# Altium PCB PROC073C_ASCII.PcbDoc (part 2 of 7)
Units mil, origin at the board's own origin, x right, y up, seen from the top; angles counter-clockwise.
Board outline 2165.35 x 2695.12 mil, 8 copper layers (Top Layer, L2_GND, L3_SIGNAL 1, L4_SIGNAL 2, L5_SIGNAL 3, L6_SIGNAL 4, L7_GND, Bottom Layer), stack 55.9 mil thick; 393 components, 319 nets, 1311 pads, 1643 vias.
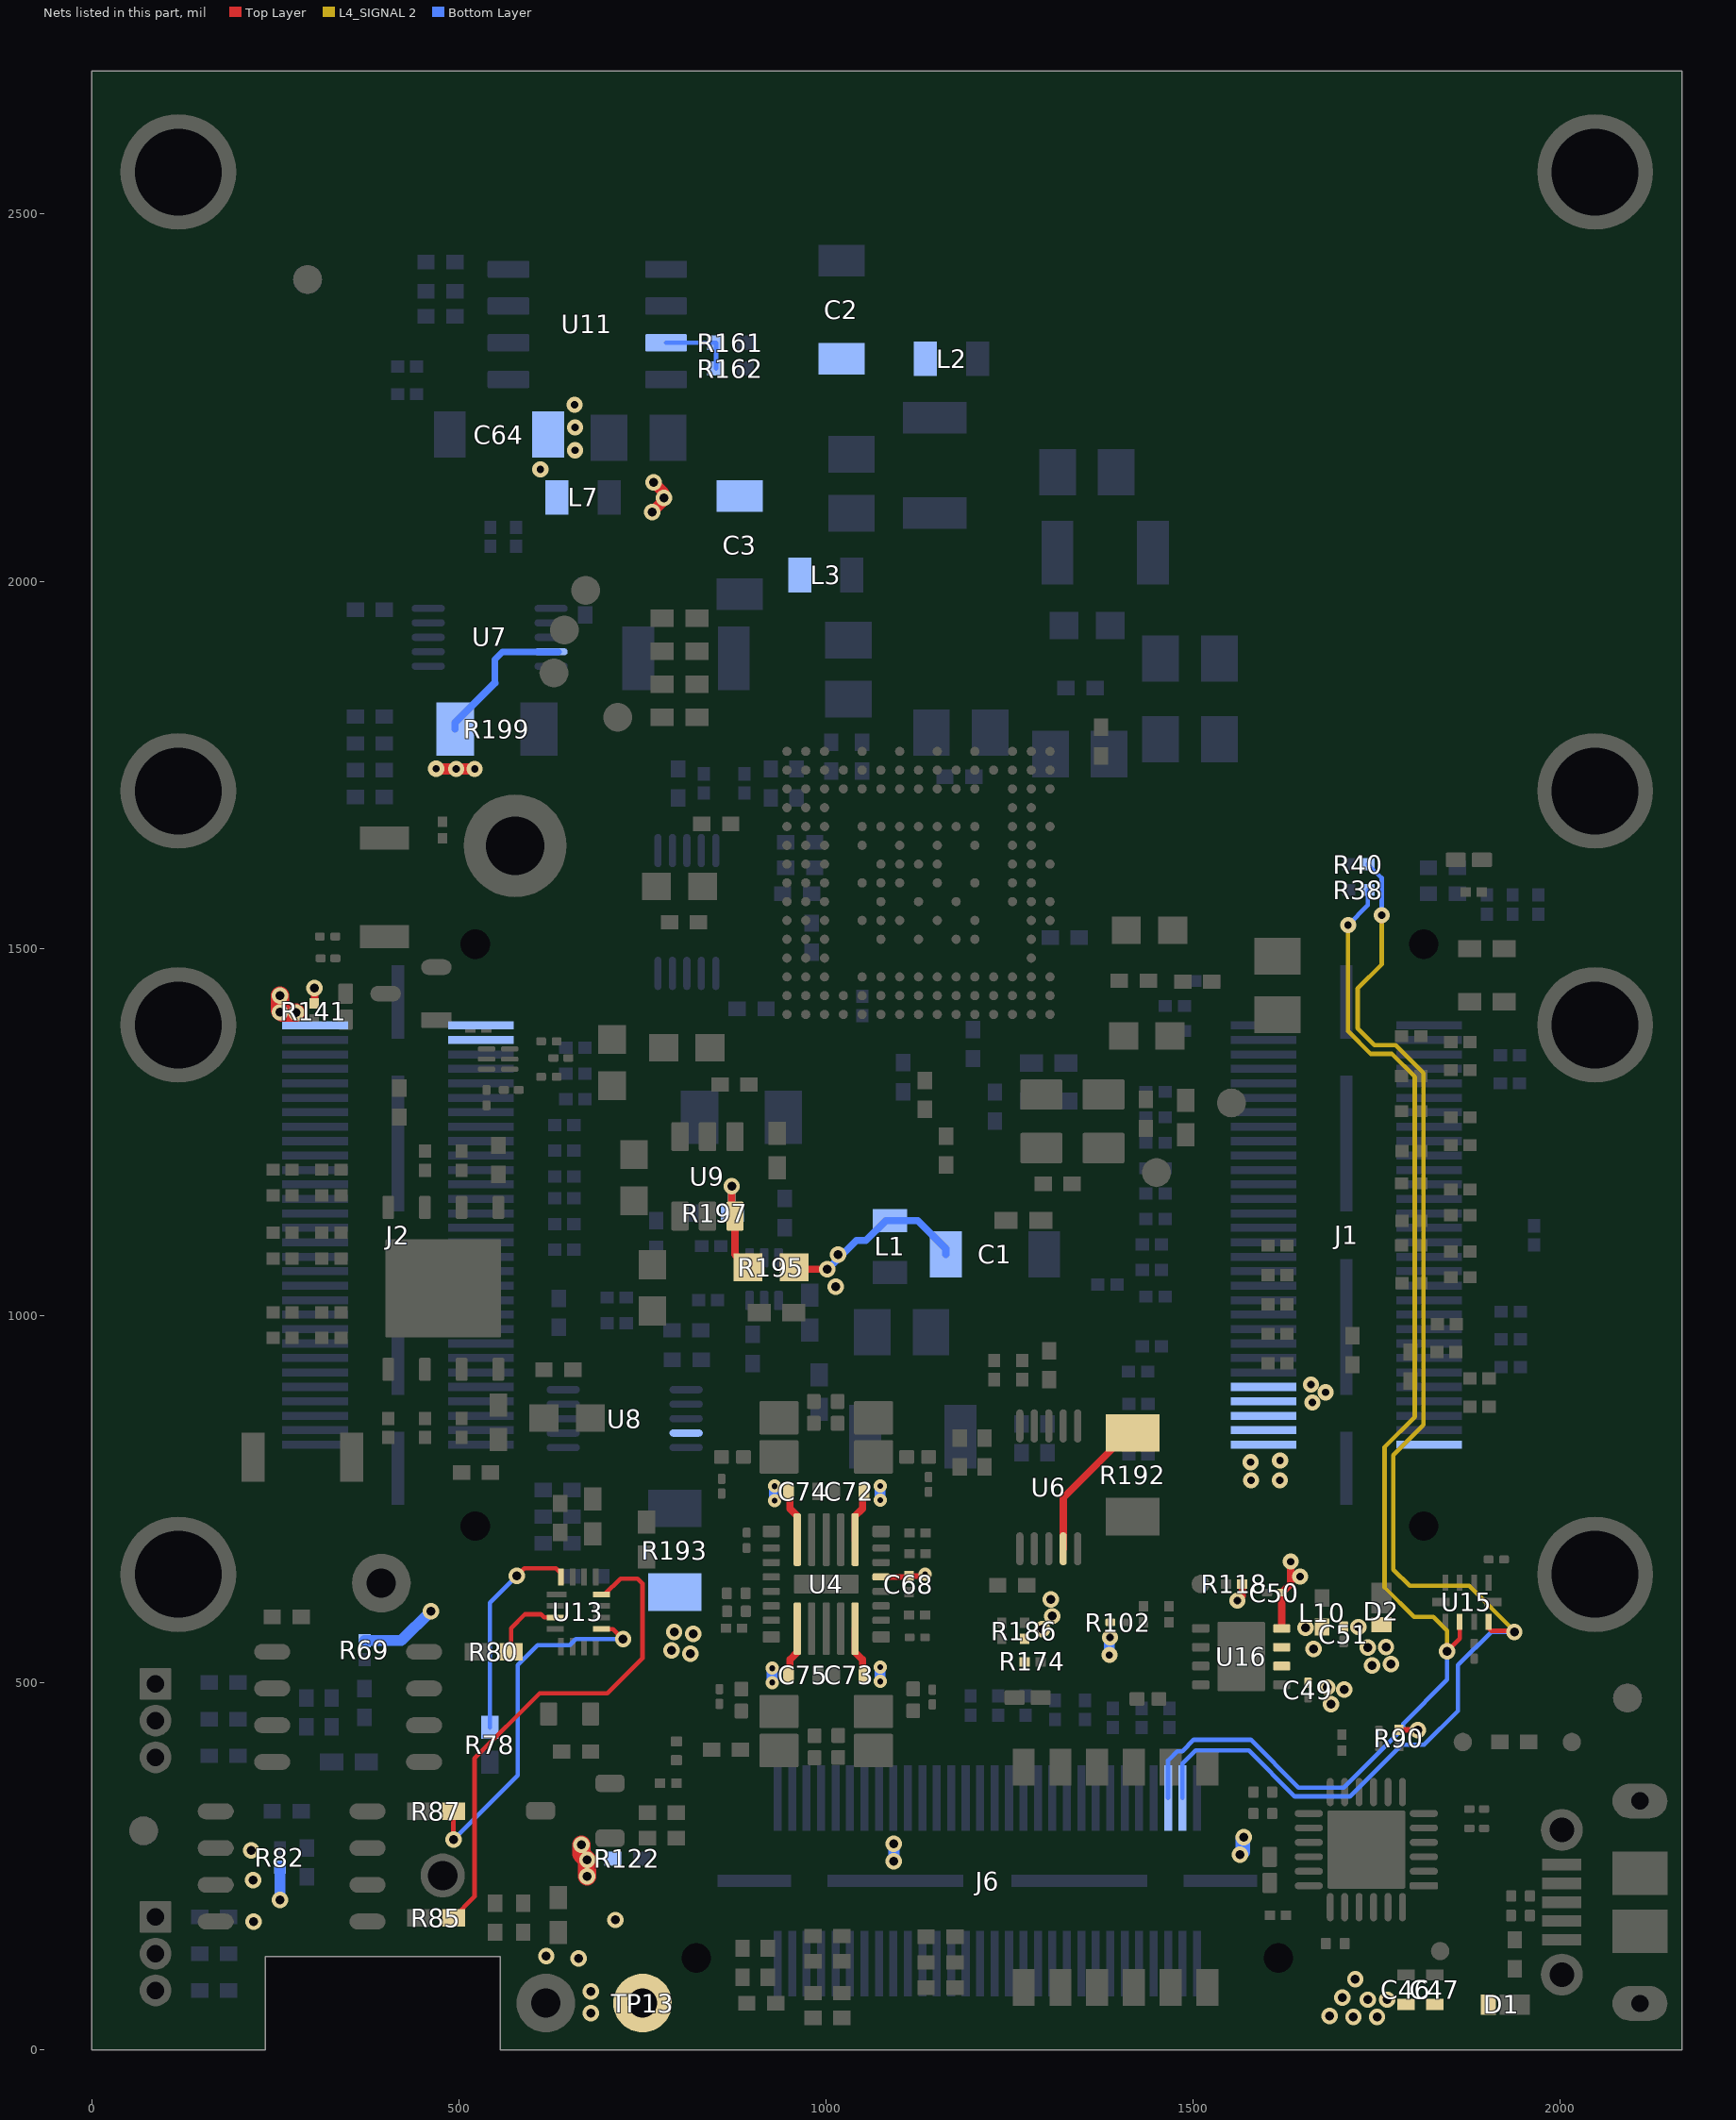
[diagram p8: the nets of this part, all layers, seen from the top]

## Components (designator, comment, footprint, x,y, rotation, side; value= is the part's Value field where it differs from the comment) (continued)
R171 "RC0201JR-07510RL" 0201L 526.8,1391.99 r180 top
R172 "ERJ-2GEJ511X" 0402L 659.82,406.64 r180 top
R173 "RC0402FR-073R83L" "FP-RC0402FR-073R83L_0402 (1005 Metric)-IPC_C" 884.8,476.65 r270 top
R174 "RC0201JR-07510RL" 0201L 1281.31,528.75 r0 top
R175 "RC0402FR-073R83L" "FP-RC0402FR-073R83L_0402 (1005 Metric)-IPC_C" 1118.8,476.93 r270 top
R176 "RC0201FR-074K99L" 0201L 1123.96,592.5 r0 top
R177 "RC0201FR-074K99L" 0201L 1124.8,676.01 r0 top
R178 "RC0402FR-073R83L" "FP-RC0402FR-073R83L_0402 (1005 Metric)-IPC_C" 872.8,807.65 r0 top
R179 "ERJ-2GEJ511X" 0402L 776.61,288.6 r180 top
R180 "RC0201JR-070RL" "FP-RC0201JR-070RL_0201 (0603 Metric)-MFG" 878.14,597.5 r0 top
R181 "RC0201JR-070RL" "FP-RC0201JR-070RL_0201 (0603 Metric)-MFG" 877.8,622 r0 top
R182 "CRCW0402100KFKED" 0402L 776.6,323.18 r0 top
R183 "RC0402FR-073R83L" "FP-RC0402FR-073R83L_0402 (1005 Metric)-IPC_C" 1124.8,807.79 r180 top
R184 "CRCW040210K0JNED" 0402 1303.12,1292.36 r180 bottom
R185 "CRCW04020000Z0ED" 0402 1303.12,1344.13 r180 bottom
R186 "RC0201JR-071KL" 0201L 1270.29,570.95 r270 top
R187 "RC0201FR-074K99L" 0201L 1124.8,704.35 r0 top
R188 "RC0201FR-074K99L" 0201L 874.94,574.5 r180 top
R189 "RR0306P-103-D" FP-RR0306P-103-D_0201-IPC_C 1124.42,562 r0 top
R190 "RR0306P-103-D" FP-RR0306P-103-D_0201-IPC_C 891.97,694.21 r90 top
R191 "RCS06030000Z0EA" 0603 738.67,1187.92 r90 top
R192 "PMR18EZPFV2L00" 1206 1417.66,783.38 r90 top
R193 "PMR18EZPFV2L00" 1206 794.24,680.61 r270 bottom
R194 "RC0201FR-071K96L" 0201L 1239.41,570.95 r90 top
R195 "MCT06030Z0000ZP500" 0603 925.25,1065.92 r180 top
R196 "CRCW0402510RJNED" 0402 932.6,1004.37 r180 top
R197 "ERJ-2RKF1003X" 0402 848.74,1139.77 r0 bottom
R198 "RC0201JR-070RL" "FP-RC0201JR-070RL_0201 (0603 Metric)-MFG" 796.29,407.65 r90 top
R199 "PMR18EZPFV2L00" 1206 552.07,1798.74 r180 bottom
R200 "PMR18EZPFV2L00" 1206 884.81,1270.12 r0 bottom
R201 "CRCW0201100KFKED" 0201L 785.2,363.4 r0 top
R202 "ERJ-2GE0R00X" 0402L 911.88,64.04 r180 top
R203 "CRCW040210K0FKED" 0402L 1002.05,77.62 r0 top
R204 "CRCW04027K87FKED" 0402L 1155.97,85.15 r0 top
R205 "CRCW040282K5FKED" 0402L 1002.05,43.89 r0 top
R206 "CRCW040210K0FKED" 0402L 920.56,118.98 r270 top
R207 "CRCW04027K87FKED" 0402L 1155.97,119.47 r0 top
R208 "CRCW040282K5FKED" 0402L 886.26,118.98 r270 top
R209 "CRCW040210K0FKED" 0402L 1002.05,155.42 r0 top
R210 "CRCW04027K87FKED" 0402L 1155.97,154.42 r0 top
R211 "CRCW040282K5FKED" 0402L 1002.05,120.94 r0 top
R212 "RC0201JR-07220RL" 0201L 1882,1576.82 r180 top
R213 "RC0201JR-07220RL" 0201L 477.94,1661.26 r90 top
R214 "RC0201JR-070RL" "FP-RC0201JR-070RL_0201 (0603 Metric)-IPC_C" 321.89,1486.65 r180 top
R215 "RR0306P-103-D" FP-RR0306P-103-D_0201-IPC_C 321.39,1516.38 r0 top
R216 "ERJ-2GE0R00X" 0402 635.54,184.1 r90 top
R217 "CRCW02010000Z0ED" 0201_Silk 326.6,1198.84 r180 top locked
R218 "CRCW02010000Z0ED" 0201_Silk 326.6,1163.84 r180 top locked
R219 "CRCW02010000Z0ED" 0201_Silk 1797.27,1044.56 r0 top
R220 "CRCW02010000Z0ED" 0201_Silk 1796.85,1095.72 r0 top
R221 "CRCW02010000Z0ED" 0201_Silk 326.6,1113.02 r180 top locked
R222 "CRCW02010000Z0ED" 0201_Silk 326.6,1078.02 r180 top locked
R223 "CRCW02010000Z0ED" 0201_Silk 326.6,1004.77 r180 top locked
R224 "CRCW02010000Z0ED" 0201_Silk 326.6,969.77 r180 top locked
R225 "CRCW02010000Z0ED" 0201_Silk 1797.27,1129.03 r0 top
R226 "CRCW02010000Z0ED" 0201_Silk 1796.85,1180.18 r0 top
R227 "CRCW02010000Z0ED" 0201_Silk 1797.27,1224.38 r0 top
R228 "CRCW02010000Z0ED" 0201_Silk 1796.85,1278.52 r0 top
R229 "CRCW02010000Z0ED" 0201_Silk 1796.85,1326.22 r0 top
R230 "CRCW02010000Z0ED" 0201_Silk 1796.85,1380.71 r0 top
S1 "218-6LPST" SW_218-6LPST 1394.21,235.15 r90 top locked
S2 "B3U-1000P" SW_B3U-1000P 287.11,807.23 r0 top
S3 "B3U-1000P" SW_B3U-1000P 398.63,1583.31 r90 top
TP1 "TESTPOINT" TP_25MIL-SMT 1836.32,134.9 r270 top
TP2 "TP_SM_1MM" TP_SM_1MM 672.85,1987.78 r90 top
TP3 "TP_SM_1MM" TP_SM_1MM 643.74,1933.67 r90 top
TP4 "TP_SM_1MM" TP_SM_1MM 716.44,1814.77 r90 top
TP5 "TP_SM_1MM" TP_SM_1MM 629.51,1875.39 r90 top
TP6 "TP_SM_1MM" TP_SM_1MM 1552,1289.77 r90 top
TP7 "TP_SM_1MM" TP_SM_1MM 1450,1194.77 r90 top
TP8 "TESTPOINT" TP_25MIL-SMT 1510.32,634.76 r90 top
TP9 "TESTPOINT" TP_25MIL-SMT 2015.61,419.58 r0 top
TP10 "TESTPOINT" TP_25MIL-SMT 1867.15,419.58 r0 top
TP11 "TESTPOINT" TP_VIA_060RND040 478.18,237.78 r180 top
TP12 "5001" Keystone5001 618.57,64.04 r0 top
TP13 "5001" Keystone5001 750.27,64.04 r0 top
TP14 "5001" Keystone5001 394.54,635.9 r0 top
U1 "IWR6843QAGABL" ABL0161B 1125.98,1589.39 r270 top
U2 "MX25V1635FZNQ" WSON-8L_6x5MM_EP 478.88,1037.19 r270 top
U3 "TMP112AQDRLRQ1" DRL0006A 915.74,1049.77 r270 bottom
U4 "LP87524JRNFRQ1" RNF0026C 1000.33,634.48 r0 top
U5 "TCAN1042HGVDQ1" D0008A_L 349.29,467.41 r180 top
U6 "INA226AIDGST" DGS0010A_L 1303.36,766.27 r270 top
U7 "INA226AIDGST" DGS0010A_L 542.07,1923.74 r0 bottom
U8 "INA226AIDGST" DGS0010A_L 725.86,859.9 r0 bottom
U9 "TPS22917DBVR" DBV0006A_N 838.74,1189.77 r90 top
U10 "INA226AIDGST" DGS0010A_L 810.59,1549.77 r270 bottom
U11 "CAT24C08WI-GT3" SOIC-8 675,2349.77 r180 bottom
U12 "TCAN1042HGVDQ1" D0008A_L 272.44,250.13 r180 top
U13 "TS3A5018RSVR" RSV0016A 662.79,596.95 r0 top
U14 "CP2105-F01-GMR" FP-CP2105-F01-GMR_QFN24-EP-IPC_A 1735.81,273.04 r180 top
U15 "TS5A23157RSER" RSE0010A 1872.76,609.98 r270 top
U16 "TPS2115ADRBR" DRB0008B 1565.44,535.87 r0 top
U17 "SN74LVC1G11DSFR" DSF0006A 553.57,1349.48 r180 top
Y1 "CX3225SA40000D0PTWCC" Kyocera_CX3225SA 1335.59,1264.77 r90 top
ZZ1 "This Assembly Note is for PCB labels only" AssemblyNoteLabel -833.57,3597.27 r0 top
ZZ2 "These assemblies are ESD sensitive, ESD precautions shall be observed." AssemblyNote -831.16,3520.11 r0 top
ZZ3 "These assemblies must be clean and free from flux and all contaminants. Use of no clean flux is not acceptable." AssemblyNote -831.16,3433.3 r0 top
ZZ4 "These assemblies must comply with workmanship standards IPC-A-610 Class 2, unless otherwise specified." AssemblyNote -835.98,3341.67 r0 top
ZZ5 "INDICATION FOR COMPONENTS D* ARE GIVEN AT THEIR CATHODE SIDE." AssemblyNote -834.59,3254.07 r0 top

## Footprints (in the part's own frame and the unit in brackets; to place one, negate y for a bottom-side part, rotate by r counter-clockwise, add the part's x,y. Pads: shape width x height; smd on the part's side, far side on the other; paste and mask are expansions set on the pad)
0201 [mm] "Data from Kemet datasheet CC101_COM dated 7/28/11"
  rect 0.46x0.42 smd mask+0: 1(-0.33,0) 2(0.33,0)
0201_033 [mm] "SMD, 2-Leads, Height 0.33mm"
  rect 0.46x0.42 smd mask+0: 1(-0.33,0) 2(0.33,0)
0201_033L [mm] "0201"
  rect 0.36x0.32 smd mask+0: 1(-0.28,0) 2(0.28,0)
0201_Silk [mm] "Data from Kemet datasheet CC101_COM dated 7/28/11"
  rect 0.46x0.42 smd mask+0: 1(-0.33,0) 2(0.33,0)
  silkscreen extent -0.75,-0.4 0.75,0.4
0201L [mm] "Data from Kemet datasheet CC101_COM dated 7/28/11"
  rect 0.36x0.32 smd mask+0: 1(-0.28,0) 2(0.28,0)
0402 [mm] "0402 from SM-752 data"
  rect 0.8x0.6 smd: 1(-0.6,0) 2(0.6,0)
  silkscreen extent -1.22,-0.52 1.22,0.52
0402_070 [mil] "SMD, 2-Leads, Body 1.2x0.7mm, Height 0.7mm"
  rect 15x24 smd: 1(-20,0) 2(20,0)
0402L [mm] "0402 from SM-752 data"
  rect 0.6x0.5 smd: 1(-0.5,0) 2(0.5,0)
0603 [mm] "0603 from SM-752 data"
  rect 1x0.95 smd: 1(-0.8,0) 2(0.8,0)
  silkscreen extent -1.52,-0.69 1.52,0.69
0805_HV [mil] "0805 with 30mil clearance between pads"
  rect 50x63 smd: 1(-40,0) 2(40,0)
  silkscreen extent -74,-40 74,40
1206 [mm] "1206 from SM-752 data"
  rect 1.3x1.85 smd: 1(-1.45,0) 2(1.45,0)
  silkscreen extent -2.4,-1.21 2.4,1.21
1206_180 [mm] "1206_180"
  rect 1.1x1.6 smd: 1(-1.7,0) 2(1.7,0)
  silkscreen extent -0.9,-1 0.9,1
1210_280 [mm] "SMD, 2-Leads, Body 3.6x2.8mm, Height 2.8mm"
  rect 1.1x2.2 smd: 1(-1.65,0) 2(1.65,0)
  silkscreen extent -0.84,-1.4 0.84,1.4
ABL0161B [mm] "BGA, 161-Balls, Body 10.4x10.4mm, Pitch 0.65mm"
  round 0.32 smd: A1(-4.55,4.55) A2(-3.9,4.55) A3(-3.25,4.55) A5(-1.95,4.55) A7(-0.65,4.55) A9(0.65,4.55) A10(1.3,4.55) A13(3.25,4.55) A14(3.9,4.55) A15(4.55,4.55) B1(-4.55,3.9) B2(-3.9,3.9) B3(-3.25,3.9) B4(-2.6,3.9) B5(-1.95,3.9) B6(-1.3,3.9) B7(-0.65,3.9) B8(0,3.9) B9(0.65,3.9) B10(1.3,3.9) B11(1.95,3.9) B12(2.6,3.9) B13(3.25,3.9) B14(3.9,3.9) B15(4.55,3.9) C1(-4.55,3.25) C2(-3.9,3.25) C3(-3.25,3.25) C4(-2.6,3.25) C5(-1.95,3.25) C6(-1.3,3.25) C7(-0.65,3.25) C8(0,3.25) C9(0.65,3.25) C13(3.25,3.25) C14(3.9,3.25) C15(4.55,3.25) D2(-3.9,2.6) D13(3.25,2.6) D14(3.9,2.6) D15(4.55,2.6) E1(-4.55,1.95) E2(-3.9,1.95) E3(-3.25,1.95) E5(-1.95,1.95) E6(-1.3,1.95) E8(0,1.95) E10(1.3,1.95) E11(1.95,1.95) E13(3.25,1.95) E14(3.9,1.95) E15(4.55,1.95) F2(-3.9,1.3) F3(-3.25,1.3) F5(-1.95,1.3) F9(0.65,1.3) F11(1.95,1.3) F13(3.25,1.3) F14(3.9,1.3) F15(4.55,1.3) G1(-4.55,0.65) G2(-3.9,0.65) G3(-3.25,0.65) G5(-1.95,0.65) G6(-1.3,0.65) G7(-0.65,0.65) G8(0,0.65) G10(1.3,0.65) G13(3.25,0.65) G14(3.9,0.65) G15(4.55,0.65) H2(-3.9,0) H3(-3.25,0) H5(-1.95,0) H7(-0.65,0) H9(0.65,0) H11(1.95,0) H13(3.25,0) H14(3.9,0) H15(4.55,0) J1(-4.55,-0.65) J2(-3.9,-0.65) J3(-3.25,-0.65) J5(-1.95,-0.65) J6(-1.3,-0.65) J7(-0.65,-0.65) J8(0,-0.65) J10(1.3,-0.65) J13(3.25,-0.65) J14(3.9,-0.65) J15(4.55,-0.65) K2(-3.9,-1.3) K3(-3.25,-1.3) K5(-1.95,-1.3) K7(-0.65,-1.3) K8(0,-1.3) K9(0.65,-1.3) K10(1.3,-1.3) K11(1.95,-1.3) K13(3.25,-1.3) K14(3.9,-1.3) K15(4.55,-1.3) L1(-4.55,-1.95) L2(-3.9,-1.95) L3(-3.25,-1.95) L5(-1.95,-1.95) L6(-1.3,-1.95) L8(0,-1.95) L10(1.3,-1.95) L13(3.25,-1.95) L14(3.9,-1.95) L15(4.55,-1.95) M2(-3.9,-2.6) M3(-3.25,-2.6) M14(3.9,-2.6) M15(4.55,-2.6) N1(-4.55,-3.25) N2(-3.9,-3.25) N3(-3.25,-3.25) N4(-2.6,-3.25) N5(-1.95,-3.25) N6(-1.3,-3.25) N7(-0.65,-3.25) N8(0,-3.25) N9(0.65,-3.25) N10(1.3,-3.25) N11(1.95,-3.25) N12(2.6,-3.25) N13(3.25,-3.25) N14(3.9,-3.25) N15(4.55,-3.25) P1(-4.55,-3.9) P2(-3.9,-3.9) P3(-3.25,-3.9) P4(-2.6,-3.9) P5(-1.95,-3.9) P6(-1.3,-3.9) P7(-0.65,-3.9) P8(0,-3.9) P9(0.65,-3.9) P10(1.3,-3.9) P11(1.95,-3.9) P12(2.6,-3.9) P13(3.25,-3.9) P14(3.9,-3.9) P15(4.55,-3.9) R1(-4.55,-4.55) R2(-3.9,-4.55) R3(-3.25,-4.55) R4(-2.6,-4.55) R5(-1.95,-4.55) R6(-1.3,-4.55) R7(-0.65,-4.55) R8(0,-4.55) R9(0.65,-4.55) R10(1.3,-4.55) R11(1.95,-4.55) R12(2.6,-4.55) R13(3.25,-4.55) R14(3.9,-4.55) R15(4.55,-4.55)
  silkscreen extent -5.3,-5.3 5.3,5.3
APHHS1005_Green [mm] "SMD, 2-Leads, Body 1x0.5mm"
  rrect20% 0.7x0.5 smd: 1(-0.45,0) 2(0.45,0)
  silkscreen extent -0.8,-0.65 1.2,0.65
AssemblyNote [mil] "Assembly Note"
AssemblyNoteLabel [mil] "Assembly Note for PCB Labels"
CE_Mark_5mm [mil] "Minimum text height for CE Mark"
CONN_105017-0001 [mm] "Molex Micro USB-B"
  rect 0.4x1.35 smd: 1(-1.3,1.35) 2(-0.65,1.35) 3(0,1.35) 4(0.65,1.35) 5(1.3,1.35)
  oval 1.2x1.9 hole 0.6 slot 1.3 at 90 deg: 6(-3.5,-1.35) 9(3.5,-1.35)
  rect 1.5x1.9 smd: 7(-1,-1.35) 8(1,-1.35)
  round 1.45 hole 0.85: 10(2.5,1.35) 11(-2.5,1.35)
  Top Layer region: 3.5,-0.4 2.3,-0.4 2.3,-2.3 3.5,-2.3
  Top Layer region: -3.5,-2.3 -2.3,-2.3 -2.3,-0.4 -3.5,-0.4
  silkscreen extent -4.1,-0.2 4.1,1.4
D0008A_L [mm] "SOIC, 8-Leads, Body 4.9x3.9mm, Pitch 1.27mm, IPC High Density"
  oval 1.25x0.55 smd: 1(-2.625,1.905) 2(-2.625,0.635) 3(-2.625,-0.635) 4(-2.625,-1.905) 5(2.625,-1.905) 6(2.625,-0.635) 7(2.625,0.635) 8(2.625,1.905)
  silkscreen extent -3.1,-2.5 0.9,2.5
DBV0006A_N [mm] "SOT23, 6-Leads, Body 2.9x1.6mm, Pitch 0.95mm, Lead Span 2.8mm, IPC Medium Density"
  rrect17% 1x0.6 smd: 1(-1.375,0.95) 2(-1.375,0) 3(-1.375,-0.95) 4(1.375,-0.95) 5(1.375,0) 6(1.375,0.95)
  silkscreen extent -1.68,-1.55 0.5,1.55
DGS0010A_L [mm] "TSSOP, 10-Leads, Body 3x3mm, Pitch 0.5mm, IPC High Density"
  oval 1.15x0.25 smd: 1(-2.125,1) 2(-2.125,0.5) 3(-2.125,0) 4(-2.125,-0.5) 5(-2.125,-1) 6(2.125,-1) 7(2.125,-0.5) 8(2.125,0) 9(2.125,0.5) 10(2.125,1)
  silkscreen extent -2.65,-1.55 0.9,1.55
DRB0008B [mm] "SON, 8-Leads, Body 3x3mm, Pitch 0.65mm, Thermal Pad 2.4x1.65mm, TI Recommended"
  rrect33% 0.6x0.3 smd: 1(-1.4,0.975) 2(-1.4,0.325) 3(-1.4,-0.325) 4(-1.4,-0.975) 5(1.4,-0.975) 6(1.4,-0.325) 7(1.4,0.325) 8(1.4,0.975)
  rrect9% 1.47x1.06 on Top Paste: 9(0,-0.63) 9(0,0.63)
  rrect6% 1.65x2.4 smd paste-1.2: 9(0,0)
  silkscreen extent -1.73,-1.73 1.73,1.73
DRL0006A [mm] "SOTFL, 6-Flat Leads, Body 1.2x1.6x0.6mm, Pitch 0.5mm, TI recommended"
  rrect33% 0.67x0.3 smd: 1(-0.74,0.5) 2(-0.74,0) 3(-0.74,-0.5) 4(0.74,-0.5) 5(0.74,0) 6(0.74,0.5)
  silkscreen extent -0.9,-0.95 0.5,0.95
DSF0006A [mm] "TI recommended land pattern"
  rrect59% 0.6x0.17 smd mask+0: 1(-0.4,0.35) 2(-0.4,0) 3(-0.4,-0.35) 4(0.4,-0.35) 5(0.4,0) 6(0.4,0.35)
  silkscreen extent -0.6,-0.63 0.6,0.63
DSN2_0603 [mm] "SMD, 2-Leads, Body 1.6x0.8mm"
  rect 0.52x0.7 smd: 1(-0.64,0)
  rect 1.05x0.7 smd: 2(0.275,0)
  silkscreen extent -1.4,-0.75 0.8,0.75
FCC_disclaimer [mil]
Fiducial10-20 [mm]
  round 1 smd mask+0: 1(0,0)
  Top Layer keep-out circle w1.178: c0,0 r0.5
FP-BSS123-7-F_SOT23-IPC_C [mm]
  rrect18% 1.059x0.547 smd paste+0 mask+0: 1(-0.877,0.915)
  rrect100% 1.059x0.547 smd paste+0 mask+0: 2(-0.877,-0.915) 3(0.877,0)
FP-CL03A105MO3NRNH_0201-IPC_C [mil]
  rrect33% 15.83x11.94 smd paste+0 mask+0: 1(-9.87,0) 2(9.87,0)
"FP-CL05A226MQ5N6J8_0402 (1005 Metric)-IPC_C" [mil]
  rrect21% 20.29x18.6 smd paste+0 mask+0: 1(-14.9,0) 2(14.9,0)
FP-CP2105-F01-GMR_QFN24-EP-IPC_A [mm]
  rrect42% 0.979x0.239 smd paste+0 mask+0: 1(-1.99,1.25)
  rrect100% 0.979x0.239 smd paste+0 mask+0: 2(-1.99,0.75) 3(-1.99,0.25) 4(-1.99,-0.25) 5(-1.99,-0.75) 6(-1.99,-1.25) 13(1.99,-1.25) 14(1.99,-0.75) 15(1.99,-0.25) 16(1.99,0.25) 17(1.99,0.75) 18(1.99,1.25)
  rrect100% 0.239x0.979 smd paste+0 mask+0: 7(-1.25,-1.99) 8(-0.75,-1.99) 9(-0.25,-1.99) 10(0.25,-1.99) 11(0.75,-1.99) 12(1.25,-1.99) 19(1.25,1.99) 20(0.75,1.99) 21(0.25,1.99) 22(-0.25,1.99) 23(-0.75,1.99) 24(-1.25,1.99)
  rrect4% 2.7x2.7 smd paste-1000 mask+0: 25(0,0)
FP-CRCW0402200RFKEDHP_0402-IPC_C [mil]
  rrect21% 20.29x18.6 smd paste+0 mask+0: 1(-14.9,0) 2(14.9,0)
"FP-GRM033R6YA104KE14D_0201 (0603 Metric)-IPC_C" [mil]
  rrect38% 13.94x10.34 smd paste+0 mask+0: 1(-10.01,0) 2(10.01,0)
FP-M50-3930342_HDR3-MFG [mm]
  rrect9% 1.1x1.1 hole 0.6 paste-1000 mask+0: 1(-1.27,1)
  round 1.1 hole 0.6 paste-1000 mask+0: 2(0,1) 3(1.27,1)
  silkscreen extent -2.97,-0.6 2.15,1.12
"FP-MCKK2012TR47M_0805 (2012 Metric)-IPC_C" [mil]
  rrect9% 45.45x53.39 smd paste+0 mask+0: 1(-26.61,0) 2(26.61,0)
"FP-RC0201JR-070RL_0201 (0603 Metric)-IPC_C" [mil]
  rrect38% 13.94x10.34 smd paste+0 mask+0: 1(-10.01,0) 2(10.01,0)
"FP-RC0201JR-070RL_0201 (0603 Metric)-MFG" [mm]
  rrect29% 0.35x0.4 smd paste+0 mask+0: 1(-0.325,0) 2(0.325,0)
"FP-RC0402FR-073R83L_0402 (1005 Metric)-IPC_C" [mil]
  rrect21% 20.29x18.6 smd paste+0 mask+0: 1(-14.9,0) 2(14.9,0)
FP-RR0306P-103-D_0201-IPC_C [mil]
  rrect37% 13.31x10.73 smd paste+0 mask+0: 1(-10.52,0) 2(10.52,0)
"FP-TMK063CG391JT-F_0201 (0603 Metric)-IPC_C" [mil]
  rrect38% 13.94x10.34 smd paste+0 mask+0: 1(-10.01,0) 2(10.01,0)
IEC_HotSurface_Small [mil]
  silkscreen extent -107,-93 107,92
Keystone5001 [mil] "For Keystone 500x miniature loop terminals"
  round 80 hole 40: 1(0,0)
  silkscreen extent -52,-52 52,52
Kyocera_CX3225SA [mm] "SMD, 4-Leads, Body 3.2x2.5mm"
  rrect10% 1.05x1.45 smd: 1(-0.925,1.075) 2(-0.925,-1.075) 3(0.925,-1.075) 4(0.925,1.075)
  silkscreen extent -1,2.28 -0.87,2.4
Label_650x200 [mil] "Thermal Transfer Label"
  round 1 on Mech13: 0(0,0)
  silkscreen extent -325,-100 325,100
MPZ2012 [mm] "TDK"
  rect 0.8x1.2 smd: 1(-0.9,0) 2(0.9,0)
RNF0026C [mm] "QFN, 26-Leads, Body 4x4.5mm, Pitch 0.5mm"
  rrect25% 0.6x0.4 smd paste-0.3: 1(-1.9,1.825) 8(-1.9,-1.825) 14(1.9,-1.825) 21(1.9,1.825)
  rrect40% 0.6x0.25 smd paste+0: 2(-1.9,1.25) 3(-1.9,0.75) 4(-1.9,0.25) 5(-1.9,-0.25) 6(-1.9,-0.75) 7(-1.9,-1.25) 15(1.9,-1.25) 16(1.9,-0.75) 17(1.9,-0.25) 18(1.9,0.25) 19(1.9,0.75) 20(1.9,1.25)
  rrect40% 0.25x1.82 smd paste-1: 9(-1,-1.54) 10(-0.5,-1.54) 11(0,-1.54) 12(0.5,-1.54) 13(1,-1.54) 22(1,1.54) 23(0.5,1.54) 24(0,1.54) 25(-0.5,1.54) 26(-1,1.54)
  rrect15% 2.24x0.66 smd paste-1: 27(0,0)
  rrect33% 0.6x0.3 on Top Paste: ""(-1.9,-1.775) ""(-1.9,1.775) ""(1.9,-1.775) ""(1.9,1.775)
  rrect33% 0.3x0.825 on Top Paste: ""(-1.575,-2.037) ""(-1.575,2.037) ""(1.575,-2.037) ""(1.575,2.037)
  rrect40% 0.25x0.81 on Top Paste: ""(-1,2.045) ""(-1,-2.045) ""(-1,-1.035) ""(-1,1.035) ""(-0.5,2.045) ""(-0.5,-2.045) ""(-0.5,-1.035) ""(-0.5,1.035) ""(0,1.035) ""(0,-2.045) ""(0,-1.035) ""(0,2.045) ""(0.5,-2.045) ""(0.5,-1.035) ""(0.5,2.045) ""(0.5,1.035) ""(1,-2.045) ""(1,-1.035) ""(1,1.035) ""(1,2.045)
  rrect15% 0.98x0.66 on Top Paste: ""(-0.59,0) ""(0.59,0)
  silkscreen extent -2.45,-2.7 2.45,2.7
RSE0010A [mm] "QFN, 10-Leads, Body 1.5x2mm, Pitch 0.5mm, TI Recommended"
  rect 0.55x0.2 smd: 1(-0.675,0.75) 2(-0.675,0.25) 3(-0.675,-0.25) 4(-0.675,-0.75) 6(0.675,-0.75) 7(0.675,-0.25) 8(0.675,0.25) 9(0.675,0.75)
  rect 0.3x0.6 smd: 5(0,-0.9) 10(0,0.9)
  silkscreen extent -1.07,-1.18 0.78,1.18
RSV0016A [mm] "QFN, 16-Leads, Body 1.8x2.6mm, Pitch 0.4mm, TI Recommended"
  rect 0.7x0.2 smd: 1(-0.75,0.6)
  rect 0.6x0.2 smd: 2(-0.8,0.2) 3(-0.8,-0.2) 4(-0.8,-0.6) 9(0.8,-0.6) 10(0.8,-0.2) 11(0.8,0.2) 12(0.8,0.6)
  rect 0.2x0.6 smd: 5(-0.6,-1.2) 6(-0.2,-1.2) 7(0.2,-1.2) 8(0.6,-1.2) 13(0.6,1.2) 14(0.2,1.2) 15(-0.2,1.2) 16(-0.6,1.2)
  silkscreen extent -1.08,-1.33 1.08,1.45
Samtec_QSH-030-01-X-D-A [mm] "Receptacle, 0.5 mm, 30x2, TH"
  rect 2.27x0.279 smd: 1(-2.865,7.25) 2(2.865,7.25) 3(-2.865,6.75) 4(2.865,6.75) 5(-2.865,6.25) 6(2.865,6.25) 7(-2.865,5.75) 8(2.865,5.75) 9(-2.865,5.25) 10(2.865,5.25) 11(-2.865,4.75) 12(2.865,4.75) 13(-2.865,4.25) 14(2.865,4.25) 15(-2.865,3.75) 16(2.865,3.75) 17(-2.865,3.25) 18(2.865,3.25) 19(-2.865,2.75) 20(2.865,2.75) 21(-2.865,2.25) 22(2.865,2.25) 23(-2.865,1.75) 24(2.865,1.75) 25(-2.865,1.25) 26(2.865,1.25) 27(-2.865,0.75) 28(2.865,0.75) 29(-2.865,0.25) 30(2.865,0.25) 31(-2.865,-0.25) 32(2.865,-0.25) 33(-2.865,-0.75) 34(2.865,-0.75) 35(-2.865,-1.25) 36(2.865,-1.25) 37(-2.865,-1.75) 38(2.865,-1.75) 39(-2.865,-2.25) 40(2.865,-2.25) 41(-2.865,-2.75) 42(2.865,-2.75) 43(-2.865,-3.25) 44(2.865,-3.25) 45(-2.865,-3.75) 46(2.865,-3.75) 47(-2.865,-4.25) 48(2.865,-4.25) 49(-2.865,-4.75) 50(2.865,-4.75) 51(-2.865,-5.25) 52(2.865,-5.25) 53(-2.865,-5.75) 54(2.865,-5.75) 55(-2.865,-6.25) 56(2.865,-6.25) 57(-2.865,-6.75) 58(2.865,-6.75) 59(-2.865,-7.25) 60(2.865,-7.25)
  round 0 hole 1.02 unplated mask+0: MH1(2.67,10.065) MH2(2.67,-10.065)
  rect 0.43x2.54 smd: MP1(0,8.065) MP4(0,-8.065)
  rect 0.43x4.7 smd: MP2(0,3.175) MP3(0,-3.175)
  silkscreen extent -3.9,-10.66 3.62,10.66
SOIC-8 [mm] "duplicate of SO-8.  SOIC, 8-Leads, Body 5.0x4.0mm (max), Pitch 1.27mm, IPC Medium Density"
  rrect17% 1.45x0.6 smd: 1(-2.725,1.905) 2(-2.725,0.635) 3(-2.725,-0.635) 4(-2.725,-1.905) 5(2.725,-1.905) 6(2.725,-0.635) 7(2.725,0.635) 8(2.725,1.905)
  silkscreen extent -3.5,-2.5 0.9,2.5
SOT-23 [mm] "SOT23, 3-Leads, Body 2.9x1.3mm, Pitch 0.95mm, Lead Span 2.5mm, IPC Medium Density"
  rrect50% 1x0.6 smd: 1(-1.2,0.95) 2(-1.2,-0.95) 3(1.2,0)
  silkscreen extent -1.62,-1.5 0.7,1.5
SW_218-6LPST [mm] "SMD, 12-Leads, Body 5.8x8.79mm"
  rect 1.27x0.76 smd: 1(-3.81,3.175) 2(-3.81,1.905) 3(-3.81,0.635) 4(-3.81,-0.635) 5(-3.81,-1.905) 6(-3.81,-3.175) 7(3.81,-3.175) 7(3.81,-3.175) 8(3.81,-1.905) 9(3.81,-0.635) 10(3.81,0.635) 11(3.81,1.905) 12(3.81,3.175)
  silkscreen extent -2.9,-4.4 2.9,4.7
SW_B3U-1000P [mm] "OMRON"
  rect 0.8x1.7 smd: 1(-1.7,0) 2(1.7,0)
  silkscreen extent -1.5,-1.25 1.5,1.25
TI_Stacked_Overlay_Small [mil]
TI_Symbol_Overlay_Small [mil]
TLMx1000_Yellow [mm] "SMD, 2-Leads, Body 1.6x0.8mm"
  rrect17% 0.6x0.8 smd: 1(-0.725,0) 2(0.725,0)
  silkscreen extent -0.98,-0.8 1.6,0.8
TP_25MIL-SMT [mil]
  round 25 smd mask+0: 1(0,0)
TP_SM_1MM [mm] "1mm Test Point, SMT"
  round 1 smd paste-0.5: 1(0,0)
TP_VIA_060RND040 [mil] "TP_VIA_060RND040"
  round 60 hole 40: 1(0,0)
WEEE_Minimum [mil] "WEEElie bin"
  silkscreen extent 22,-71 54,74
WSON-8L_6x5MM_EP [mm] "SMD, 8-Leads, Body 6x5mm, Pitch 1.27mm"
  rrect25% 0.8x0.4 smd: 1(-2.8,1.905) 2(-2.8,0.635) 3(-2.8,-0.635) 4(-2.8,-1.905) 5(2.8,-1.905) 6(2.8,-0.635) 7(2.8,0.635) 8(2.8,1.905)
  rrect3% 3.4x4 smd paste-3: 9(0,0)
  rrect7% 1.468x1.698 on Top Paste: ""(-0.834,0.949) ""(-0.834,-0.949) ""(0.834,0.949) ""(0.834,-0.949)
  silkscreen extent -3.2,-2.7 3.2,2.7

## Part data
C1 C2 C3 C64: library part CMP-0008770-2, "CAP, CERM, 22 uF, 6.3 V, +/- 10%, X7R, AEC-Q200 Grade 1, 1206"
C4 C5 C6 C9 C10 C11 C12 C14 C16 C19 C20 C21 C28 C29: library part CMP-0078265-1, "CAP, CERM, 0.22 µF, 16 V,+/- 10%, X7R, AEC-Q200 Grade 1, 0402"
C7 C8 C13 C15 C23 C24: library part CMP-0085348-1, "CAP, CERM, 10 µF, 10 V,+/- 20%, X7R, 0805"
C17 C27: library part CMP-0007134-5, "CAP, CERM, 2.2 uF, 6.3 V, +/- 10%, X7R, AEC-Q200 Grade 1, 0603"
C18 C22 C35: library part CMP-0007136-5, "CAP, CERM, 1 uF, 16 V, +/- 10%, X7R, AEC-Q200 Grade 1, 0603"
C25 C26: library part CMP-0006351-2, "CAP, CERM, 0.1 uF, 16 V, +/- 10%, X7R, 0402"
C30: library part CMP-0006352-2, "CAP, CERM, 0.01 uF, 25 V, +/- 10%, X7R, 0402"
C31: library part CMP-0064969-1, "CAP, CERM, 0.1 uF, 10 V,+/- 10%, X7S, 0201"
C32 C33: library part CMP-0006367-2, "CAP, CERM, 4.7 pF, 50 V, +/- 2%, C0G/NP0, 0402"
C34 C36 C57 C58 C59 C63 C65: library part CMP-0006325-2, "CAP, CERM, 0.1 uF, 50 V, +/- 10%, X7R, AEC-Q200 Grade 1, 0402"
C37 C38 C40 C41 C43: library part CMP-0078241-1, "CAP, CERM, 0.1 µF, 10 V,+/- 10%, X7R, 0402"
C39 C42: library part CMP-0006361-2, "CAP, CERM, 4700 pF, 50 V, +/- 10%, X7R, AEC-Q200 Grade 1, 0402"
C44 C45 C48 C49 C50 C52 C53: library part CMP-0086440-1, "Cap Ceramic 0.1uF 35V X5R 10% Pad SMD 0201 85C T/R"
C46 C47 C72 C73 C74 C75: library part CMP-0006339-4, "CAP, CERM, 10 uF, 10 V, +/- 20%, X5R, 0402"
C51: library part CMP-0086446-1, "1µF ±20% 16V Ceramic Capacitor X5R 0201"
C54 C55 C56 C60: library part CMP-0086438-1, "CAP CER 390PF 25V C0G/NP0 0201"
C61 C62 C66 C67: library part CMP-0086447-1, "CAP CER 22UF 6.3V X5R 0402"
C68: library part CMP-0009781-1, "CAP, CERM, 0.22 uF, 10 V, +/- 20%, X5R, 0201"
C69: library part CMP-0007111-4, "CAP, CERM, 1 uF, 6.3 V, +/- 10%, X7R, 0603"
C70: library part CMP-0006858-4, "CAP, CERM, 0.1 uF, 50 V, +/- 5%, X7R, 0603"
C71: library part CMP-0006332-2, "CAP, CERM, 1000 pF, 100 V, +/- 10%, X7S, AEC-Q200 Grade 1, 0402"
C76 C78 C80 C82: library part CMP-0009174-2, "CAP, CERM, 22 uF, 16 V, +/- 10%, X7R, 1210"
C77 C79 C81 C83: library part CMP-0008017-2, "CAP, CERM, 10 uF, 10 V, +/- 10%, X7R, 0805"
"CAUTION HOT SURFACE1": library part CMP-0074837-1, "IEC 61010-1 Hot Surface Warning"
D1 D2: library part CMP-0028829-2, "Diode, Schottky, 30 V, 2 A, 2-XFDFN"
D3: library part CMP-0078196-2, "LED, Yellow, SMD"
D4 D5 D6 D7: library part CMP-0067682-2, "LED, Green, SMD"
FID1 FID2 FID3 FID4 FID5 FID6: library part CMP-0077181-1, "Fiducial mark.  There is nothing to buy or mount."
J1 J2 J6: library part CMP-0075524-1, "Receptacle, 0.5 mm, 30x2, Gold, TH"
J3 J4: library part CMP-0087785-1, "CONN HEADER R/A 3POS 1.27MM"
J5: library part CMP-0055293-1, "Connector, Receptacle, Micro-USB Type B, R/A, Bottom Mount SMT"
L1 L2 L3 L7: library part CMP-0003427-2, "Ferrite Bead, 100 ohm @ 100 MHz, 4 A, 0805"
L4 L5 L6 L8: library part CMP-0087178-1, "FIXED IND 470NH 4.5A 39 MOHM SMD"
L9 L10 L11 L12: library part CMP-0078934-1, "Inductor, Ferrite Bead, Ferrite, 2.2 A, 0.035 ohm, AEC-Q200 Grade 1, SMD"
LBL1: library part CMP-0003625-1, "Thermal Transfer Printable Labels, 0.650\" W x 0.200\" H - 10,000 per roll"
Logo1 Logo5: library part CMP-0074838-1, "Texas Instrument Corporate Signature"
Logo2: library part CMP-0074844-1
LOGO3: library part CMP-0074847-1, "FCC_disclaimer"
Logo4: library part CMP-0074769-1
Q1: library part CMP-0087176-1, "MOSFET N-CH 100V 170MA SOT23-3"
Q2: library part CMP-0000947-2, "MOSFET, N-CH, 100 V, 0.17 A, SOT-23"
R1 R195: library part CMP-0025884-3, "RES, 0, 5%, 0.125 W, 0603"
R2 R14 R44 R49 R52 R53 R54 R70 R71 R83 R84 R88 R94 R101 R103 R104 R105 R106 R107 R112 R113 R114 R115 R116 R117 R139 R142 R145 R146 R147 R152 R157 R158 R161 R162 R203 R206 R209: library part CMP-0025958-3, "RES, 10.0 k, 1%, 0.063 W, AEC-Q200 Grade 0, 0402"
R3 R43 R72 R73 R74 R75 R76 R77 R78 R80 R85 R87 R122 R202 R216: library part CMP-0026992-3, "RES, 0, 5%, 0.1 W, AEC-Q200 Grade 0, 0402"
R4 R5 R6 R7 R8 R9 R10 R11 R12 R13 R16 R22 R24 R25 R29 R30 R31 R32 R33 R34 R35 R36 R37 R38 R39 R40 R41 R42 R55 R56 R58 R59 R60 R61 R62 R63 R64 R65 R66 R67 R69 R82 R108 R109 R110 R111 R131 R133 R134 R135 R136 R137 R140 R143 R144 R159 R160 R217 R218 R219 R220 R221 R222 R223 R224 R225 R226 R227 R228 R229 R230: library part CMP-0027008-4, "RES, 0, 5%, 0.05 W, 0201"
R15 R17 R18 R19 R20 R21 R23 R26 R27 R28 R124 R125 R126 R127 R128 R129 R130 R132 R148 R149 R163 R164 R166 R167 R168 R170: library part CMP-0078192-2, "RES, 20.0, 1%, 0.05 W, 0201"
R45 R46 R47 R48 R51: library part CMP-0027275-3, "RES, 33.2, 1%, 0.05 W, 0201"
R50: library part CMP-0026395-2, "RES, 47.5 k, 1%, 0.063 W, AEC-Q200 Grade 0, 0402"
R57 R151 R185: library part CMP-0026822-3, "RES, 0, 5%, 0.063 W, AEC-Q200 Grade 0, 0402"
R68 R79 R81 R86: library part CMP-0026491-2, "RES, 61.9, 1%, 0.063 W, AEC-Q200 Grade 0, 0402"
R89: library part CMP-0026938-5, "RES, 4.7 k, 5%, 0.063 W, AEC-Q200 Grade 0, 0402"
R90 R93 R176 R177 R187 R188: library part CMP-0027745-1, "RES, 4.99 k, 1%, 0.05 W, 0201"
R91 R92 R96 R97 R98 R180 R181 R198 R214: library part CMP-0086442-2, "RES SMD 0 OHM JUMPER 1/20W 0201"
R95 R100 R102 R123 R138 R165 R189 R190 R215: library part CMP-0088002-1, "10 kOhms ±0.5% 0.05W, 1/20W Chip Resistor 0201 (0603 Metric)  Thin Film"
R99 R212 R213: library part CMP-0027072-1, "RES, 220, 5%, 0.05 W, 0201"
R118 R141 R171 R174: library part CMP-0027137-1, "RES, 510, 5%, 0.05 W, 0201"
R119 R120 R201: library part CMP-0027261-3, "RES, 100 k, 1%, 0.05 W, 0201"
R121: library part CMP-0087183-1, "RES SMD 200 OHM 1% 1/5W 0402"
R150 R169 R184: library part CMP-0026825-5, "RES, 10 k, 5%, 0.063 W, AEC-Q200 Grade 0, 0402"
R153 R154 R155 R156 R182: library part CMP-0025950-3, "RES, 100 k, 1%, 0.063 W, AEC-Q200 Grade 0, 0402"
R172 R179: library part CMP-0078212-1, "RES, 510, 5%, 0.1 W, AEC-Q200 Grade 0, 0402"
R173 R175 R178 R183: library part CMP-0086444-2, "RES Thick Film SMD 3.83O 1% 1/16W 0402 200ppm/°C"
R186: library part CMP-0027052-1, "RES, 1.0 k, 5%, 0.05 W, 0201"
R191: library part CMP-0081973-1, "RES, 0, 0%, 0.25 W, AEC-Q200 Grade 0, 0603"
R192 R193 R199 R200: library part CMP-0081623-1, "RES, 0.002, 1%, 1 W, AEC-Q200 Grade 0, 1206"
R194: library part CMP-0027452-1, "RES, 1.96 k, 1%, 0.05 W, 0201"
R196: library part CMP-0026944-3, "RES, 510, 5%, 0.063 W, AEC-Q200 Grade 0, 0402"
R197: library part CMP-0026659-1, "RES, 100 k, 1%, 0.1 W, 0402"
R204 R207 R210: library part CMP-0026557-2, "RES, 7.87 k, 1%, 0.063 W, AEC-Q200 Grade 0, 0402"
R205 R208 R211: library part CMP-0026574-2, "RES, 82.5 k, 1%, 0.063 W, AEC-Q200 Grade 0, 0402"
S1: library part CMP-0002304-1, "Switch, SPST, Slide, Off-On, 6 Pos, 0.025A, 24V, SMD"
S2 S3: library part CMP-0002150-2, "SWITCH TACTILE SPST-NO 0.05A 12V"
TP1 TP8 TP9 TP10 TP11: library part CMP-0078143-3, "TEST POINT.  No entry in BOM."
TP2 TP3 TP4 TP5 TP6 TP7: library part CMP-0003825-1, "1mm Test Point, SMT"
TP12 TP13 TP14: library part CMP-0055138-1, "Test Point, Miniature, Black, TH"
U1: library part CMP-0081105-1, "IWR1843QAGABL, ABL0161B (FCBGA-161)"
U2: library part CMP-0079267-1, "2.3V-3.6V, 16M-BIT [x 1/x 2/x 4] CMOS FLASH Memory, WSON-8"
U3: library part CMP-0067398-2, "Automotive Grade, 1.4V-Capable +/-0.5degC Temperature Sensor with Alert Function and I2C/SMBus, DRL0006A (SOT-OTHER-6)"
U4: library part CMP-0079120-2, "4-A + 2.5-A + Two 1.5-A Buck Converters With Integrated Switches, RNF0026C (VQFN-HR-26)"
U5 U12: library part CMP-0075992-1, "Automotive Fault Protected CAN Transceiver With Flexible Data-Rate, D0008A (SOIC-8)"
U6 U7 U8 U10: library part CMP-0037978-1, "High-Side Measurement, Bi-Directional Current / Power Monitor with I2C Interface, 2.7 to 5.5 V, -40 to 125 degC, 10-pin SOP (DGS10), Green (RoHS & no Sb/Br)"
U9: library part CMP-0077265-1, "5.5-V, 2-A, 80 mohm Low Leakage Load Switch with RCB and Programmable Rise Time, DBV0006A (SOT-23-6)"
U11: library part CMP-0005309-2, "IC, EEPROM, 8KBIT, 400KHZ, 8SOIC"
U13: library part CMP-0067415-1, "10-Ohm Quad SPDT Analog Switch, RSV0016A (UQFN-16)"
U14: library part CMP-0087172-1, "I/O Controller Interface IC USB to Dual UART bridge"
U15: library part CMP-0074545-1, "Dual 10-ohm SPDT Analog Switch, RSE0010A (UQFN-10)"
U16: library part CMP-0043358-3, "Dual In / Single Out Autoswitching Power Mux, 2.8 to 5.5 V, -40 to 85 degC, 8-pin SON (DRB), Green (RoHS & no Sb/Br)"
U17: library part CMP-0051215-4, "Single 3-Input Positive-AND Gate, DSF0006A, LARGE T&R"
Y1: library part CMP-0004694-3, "Crystal, 40 MHz, 8pF, SMD"
ZZ1: library part CMP-0003616-3
ZZ2: library part CMP-0077236-1
ZZ3: library part CMP-0077237-1
ZZ4 ZZ5: library part CMP-0077238-1

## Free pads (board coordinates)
  round 157.48 hole 118.11: TH1(118.11,2557.33) TH2(118.11,1714.58) TH3(118.11,1395.91) TH4(118.11,647.88) TH5(2047.24,647.88) TH6(2047.24,1395.91) TH7(2047.24,1714.58) TH8(2047.24,2557.33)
  round 140 hole 80: TH9(576.76,1639.96)

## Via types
v1: diameter 15.74, hole 5.9, Top Layer to L2_GND, tented both sides, 894 vias
v2: diameter 22.4, hole 12.2, Top Layer to Bottom Layer, tented both sides, 510 vias
v3: diameter 18, hole 8, Top Layer to Bottom Layer, tented both sides, 74 vias
v4: diameter 15.75, hole 5.9, Top Layer to L2_GND, tented both sides, 72 vias
v5: diameter 22, hole 10, Top Layer to Bottom Layer, tented both sides, 61 vias
v6: diameter 19.68, hole 7.87, Top Layer to Bottom Layer, 16 vias
v7: diameter 15.74, hole 5.9, Top Layer to L2_GND, tented top, 14 vias
v8: diameter 20, hole 10, Top Layer to Bottom Layer, tented both sides, 1 vias
v9: diameter 15.75, hole 5.9, Top Layer to L2_GND, tented top, 1 vias

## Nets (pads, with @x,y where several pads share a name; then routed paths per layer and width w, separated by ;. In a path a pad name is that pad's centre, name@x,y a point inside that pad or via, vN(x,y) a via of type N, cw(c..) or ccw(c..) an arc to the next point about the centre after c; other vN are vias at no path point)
5V_IN: C68.1 C72.1 C73.1 C74.1 C75.1 D2.1 R69.2 R82.2 R90.1 R141.1 R174.1 R186.2 U4.9 U4.13 U4.18 U4.22 U4.26 | length 612.3
  Top Layer w7.87: R90.1@1780.23,436 v2(1806.07,436)
  Top Layer w8: U4.18@1075.13,644.32 1111.76,644.32 C68.1@1112.94,645.5 1132.44,645.5 v3(1134.94,648)
  Top Layer w9.84: R141.1@302.97,1425.21 303.7,1425.95 v2(303.7,1446.25)
  Top Layer w10: C75.1@950.83,509.23 950.83,531.64 960.96,541.77 U4.9@960.96,573.85 ; C74.1@950.83,759.73 950.83,737.32 960.96,727.19 U4.26@960.96,695.11 ; U4.13@1039.7,573.85 1039.7,541.77 1049.83,531.64 C73.1@1049.83,510.63 ; U4.22@1039.7,695.11 1039.7,727.19 1049.83,737.32 C72.1@1049.83,759.73 ; D2.1@1756.62,579.5 D2.1@1756.89,579.22
  Bottom Layer w15: v2(256.48,204.55) R82.2@256.48,249.15 ; R69.2@371.69,557.65 421.8,557.65 v2(462.02,597.88) ; v3(926.91,500.56) v3(926.91,520.05) ; v3(930.04,748.38) v3(930.04,767.88) ; v3(1073.76,748.85) v3(1073.76,768.34) ; v3(1073.78,502.01) v3(1073.78,521.51)
  other v2: 679.79,50.23 679.82,80.01 662.96,125.15 619.12,127.89 220.63,174.93 713.35,177.24 219.85,231.37 217.28,272.11 1743.3,523.8 1769.35,525.83 1737.62,548.12 1762.55,549.06 1294.35,573.01 1308.29,590.91 1305.88,613.81
5V_IN_SW: C51.1 L10.1 R118.1 U16.7 | length 25.6
  Top Layer w10: v5(1560.32,612.12) 1560.71,612.12 1566.81,618.22 R118.1@1566.81,634.76
  other v2: 1663.7,546.47 1653.21,574.91 1724.82,576.15
5V_IN_USB: C46.2 C47.1 C49.1 D1.1 U16.6
  other v2: 1718.17,45.01 1750.34,45.47 1685.95,46.78 1737.99,68.7 1764,68.7 1703.04,71.54 1720.73,96.49 1687.77,471.34 1705.7,490.92 1682.36,493.91
A2: R161.1 R162.2 U11.3 | length 103
  Bottom Layer w6: U11.3@782.28,2324.77 R161.1@850.32,2324.77 R162.2@850.31,2289.77
CAN1_RX: R80.1 U13.3 | length 101.9
  Top Layer w6: R80.1@571.12,542.41 571.12,574.38 590.27,593.53 611.78,593.53 616.23,589.07 U13.3@631.29,589.07
CAN1_TX: R78.1 U13.16 | length 293.8
  Top Layer w6: v2(579,645.82) 589.12,655.94 632.4,655.94 639.17,649.17 U13.16@639.17,644.19
  Bottom Layer w6: R78.1@542.39,439.33 542.39,609.21 v2(579,645.82)
CAN2_RX: R87.1 U13.9 | length 506.3
  Top Layer w6: v2(492.68,286.47) R87.1@492.68,325.13 ; U13.9@694.28,573.33 710.16,573.33 v2(723.85,559.64)
  Bottom Layer w6: v2(492.68,286.47) 580.32,374.11 580.32,524.44 607.09,551.21 650.88,551.21 659.31,559.64 v2(723.85,559.64)
CAN2_TX: R85.1 U13.12 | length 683.4
  Top Layer w6: R85.1@492.68,180.13 521.45,208.9 521.45,397.25 610.17,485.97 702.45,485.97 750.12,533.64 750.12,635.25 743.29,642.08 720.28,642.08 698.77,620.57 U13.12@694.28,620.57
CB_PMIC_1V0: C2.2 C3.2 J1.1 J1.3 L2.1 L3.1 R199.2 U7.9 | length 313.4
  Top Layer w15: v5@469.21,1744.62 v5(496.61,1744.62) v5@521.72,1744.62 ; v2(763.36,2094.51) 779.37,2110.53 v2(779.37,2113.76) 779.37,2120.38 v2(765.2,2134.55)
  Bottom Layer w9: 549.11,1861.53 549.11,1893.78 559.39,1904.05 U7.9@635.73,1904.05
  Bottom Layer w10: R199.2@494.99,1798.74 494.99,1807.41 549.11,1861.53
  other v5: 1578.65,775.81 1617.93,775.93 1578.32,800.67 1618.28,802.87 469.21,1744.78 521.72,1744.62
CB_PMIC_1V2: C64.2 J1.5 J1.7 L7.1 R193.2 U8.9
  other v2: 815.5,539.92 789.54,544.31 819.27,566.78 793.26,569.32
  other v5: 611.1,2152.44 658.36,2178.4 658.35,2209.65 657.55,2240.37
CB_PMIC_1V8: C1.2 J1.9 L1.1 R192.2 R195.1 U6.9 | length 459.7
  Top Layer w10: R195.1@956.75,1065.92 960.23,1062.44 961.14,1063.36 v2(1001.51,1063.36) ; U6.9@1323.04,682.61 1323.04,751.88 1411.63,840.47 R192.2@1417.66,840.47
  Bottom Layer w10: v2(1001.51,1063.36) 1002.3,1063.36 1041.38,1102.44 1054.4,1102.44 1081.55,1129.59 L1.1@1087.23,1129.59 1124.85,1129.59 1163.22,1091.22 C1.2@1163.22,1083.72
  other v2: 1013.46,1039.78 1016.58,1083.45
  other v5: 1662.27,882.01 1680.41,895.76 1660.54,906.14
CONN_5V: C50.1 J1.2 J2.58 J2.59 J2.60 R102.1 R122.1 TP13.1 U16.8 | length 261.6
  Top Layer w10: U16.8@1620.56,574.26 C50.1@1620.56,622.77 1632.9,635.11 v5(1632.9,665.21)
  Top Layer w25: v2(256.29,1435.93) 256.29,1415.66 259.45,1412.5 v2(278.68,1412.5) ; v2(666.75,279.69) 666.75,267.23 v2(675,258.98) 676.89,257.09 674.57,254.77 v2(674.57,236.68)
  Bottom Layer w15: v2@1092.45,257.11 v2(1092.45,280.85) ; v5(1385.91,538.02) v5@1385.91,561.95
  Bottom Layer w20: v2(1563.64,266.36) 1567.5,270.21 1567.5,288.51 v2(1568.93,289.94)
  other v2: 1091.96,257.11 256.29,1413.11
  other v5: 1386.72,561.95 1645.49,644.91
CONN_RS232RX: J6.55 R38.1 U15.7 | length 1790.6
  Top Layer w6: v2(1845.83,543.12) 1862.92,560.21 U15.7@1862.92,583.41
  L4_SIGNAL 2 w6: v5(1710.89,1531.87) 1710.89,1387.43 1741.74,1356.58 1770.68,1356.58 1801.76,1325.5 1801.76,862.45 1760.57,821.26 1760.57,630.1 1800.88,589.78 1827.25,589.78 1845.83,571.2 v2(1845.83,543.12)
  Bottom Layer w6: J6.55@1465.8,343.28 1465.8,394.32 1478.49,407.01 1485.21,407.01 1500.84,422.64 1578.23,422.64 1643.44,357.43 1704.87,357.43 1785.87,438.43 1785.87,444.37 1845.83,504.33 v2(1845.83,543.12) ; v5(1710.89,1531.87) 1737.99,1558.97 R38.1@1737.99,1579.77
CONN_RS232TX: J6.57 R40.1 U15.9 | length 1961.3
  Top Layer w6: U15.9@1902.29,583.41 1902.29,574.97 1906.32,570.94 1937.23,570.94 v2(1937.23,569.58)
  L4_SIGNAL 2 w6: v5(1756.72,1545.42) 1756.72,1478.23 1723.92,1445.43 1723.92,1391.37 1746.71,1368.58 1775.65,1368.58 1813.76,1330.47 1813.76,851.6 1772.57,810.41 1772.57,654.42 1794.82,632.17 1876,632.17 1937.23,570.94 v2(1937.23,569.58)
  Bottom Layer w6: J6.57@1485.49,343.28 1485.49,390.31 1503.17,408 1575.9,408 1638.46,345.43 1713.57,345.43 1783.95,415.8 1814.44,415.8 1860.43,461.79 1860.43,524.14 1905.87,569.58 v2(1937.23,569.58) ; R40.1@1737.99,1614.77 1756.72,1596.05 v5(1756.72,1545.42)
EN_3V3: R195.2 R197.2 U9.3 | length 157
  Top Layer w10: v2(871.6,1176.58) 871.6,1140.18 U9.3@876.14,1135.64 876.14,1083.53 R195.2@893.75,1065.92
  Bottom Layer w10: v2(871.6,1176.58) 871.6,1140.53 R197.2@872.36,1139.77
